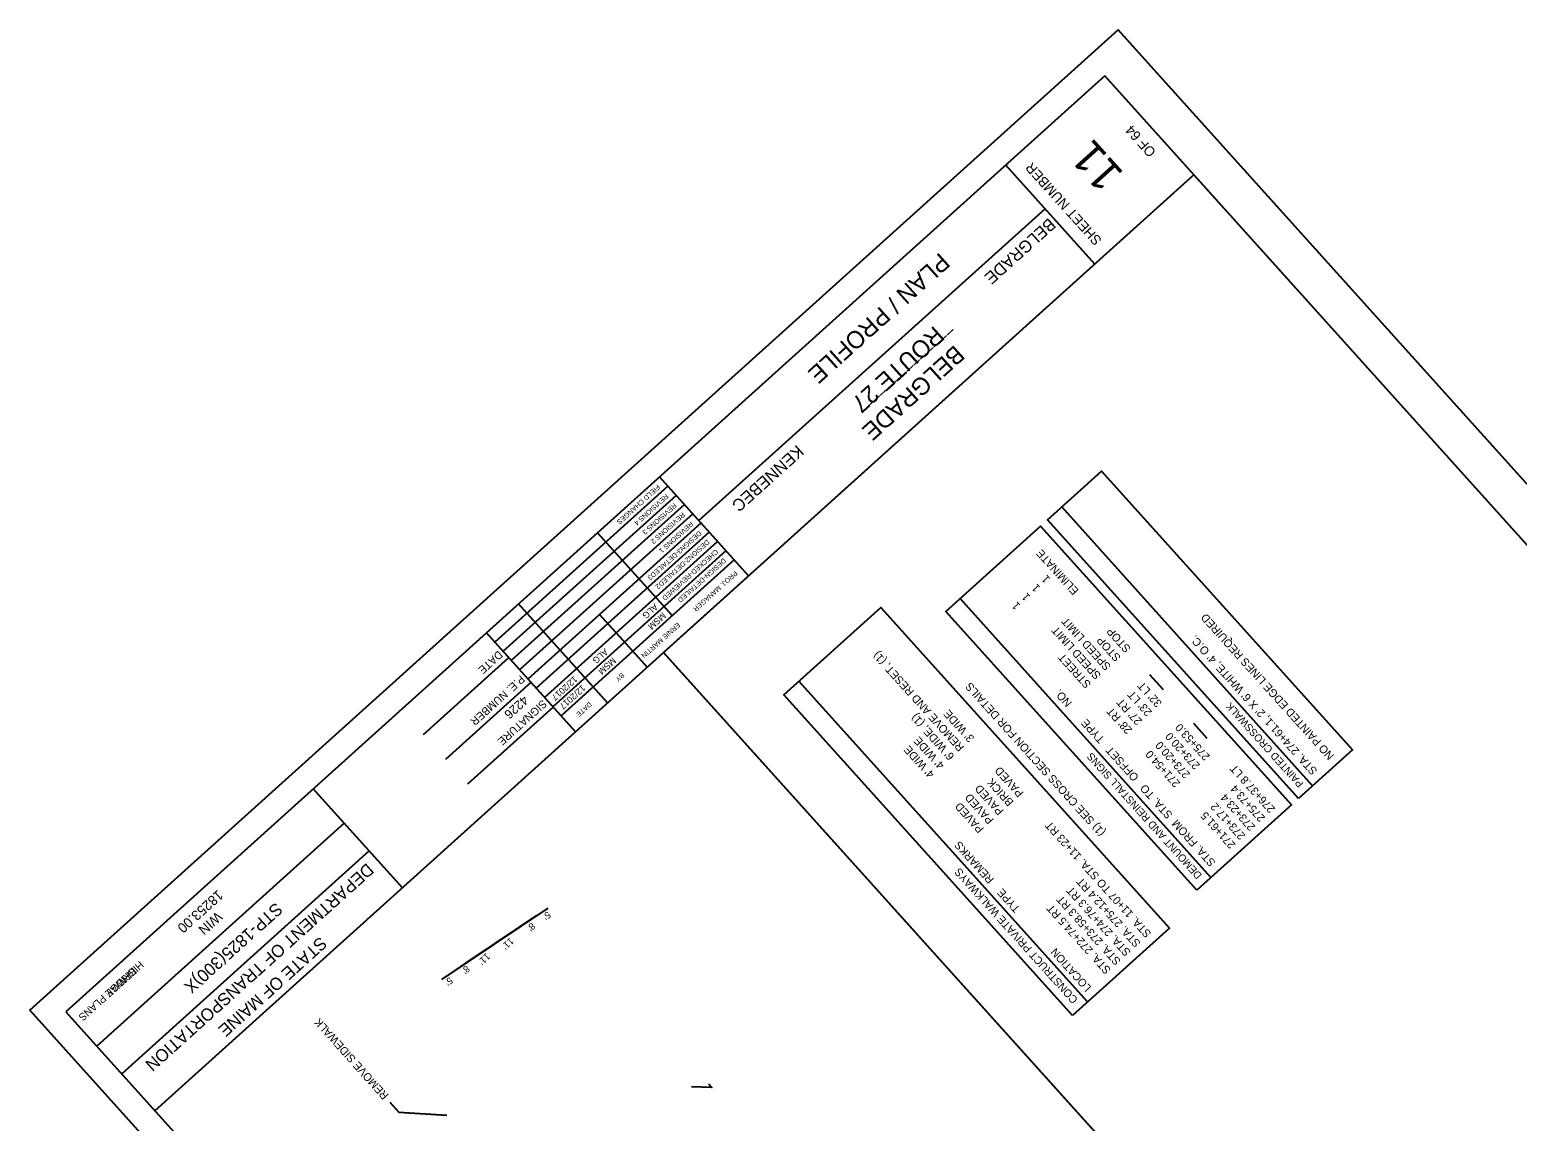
# Model space of a CAD drawing. Extents: x 1111534 to 1112511, y 616515 to 617514.
# Drawn here: x 1111534 to 1112092, y 617105 to 617514 of the extents above; entities that cross this region are included whole.
import ezdxf

# ---------------------------------------------------------------- set-up
doc = ezdxf.new("R2010")
doc.units = 0
for name, color, linetype in [('ANNOTATION', 7, 'Continuous'), ('BORDER', 7, 'Continuous'), ('BRIDGE_TITLE', 7, 'Continuous'), ('CLIPS', 7, 'Continuous'), ('HIGHWAY_TITLE', 7, 'Continuous'), ('PLOT BOUNDARY', 7, 'Continuous')]:
    doc.layers.add(name, color=color, linetype=linetype)

msp = doc.modelspace()

# ---------------------------------------------------------------- linework, layer by layer
at = {"layer": 'ANNOTATION'}
for p, q in [((1112015.33, 617230.49), (1111921.1, 617335.15)), ((1111977.12, 617196.09), (1111882.89, 617300.74)), ((1111930.75, 617149.36), (1111822.4, 617269.7)), ((1111959.27, 617266.5), (1111954.21, 617272.12)), ((1111975.72, 617248.23), (1111970.66, 617253.85)), ((1111723.81, 617181.68), (1111717.24, 617177.27)), ((1111723.81, 617181.68), (1111717.24, 617177.27)), ((1111718.41, 617178.05), (1111723.73, 617181.63)), ((1111714.68, 617175.55), (1111708.11, 617171.13)), ((1111711.91, 617173.69), (1111717.24, 617177.27)), ((1111705.55, 617169.41), (1111698.97, 617165)), ((1111702.78, 617167.55), (1111708.11, 617171.13)), ((1111698.91, 617164.95), (1111692.33, 617160.53)), ((1111693.65, 617161.42), (1111698.97, 617165))]:
    msp.add_line(p, q, dxfattribs=at)
for points in [[(1112009.98, 617225.68), (1111915.75, 617330.33), (1111936.04, 617348.6), (1112030.27, 617243.94)], [(1111971.77, 617191.27), (1111877.54, 617295.92), (1111913.11, 617327.95), (1112007.34, 617223.29)], [(1111925.12, 617144.29), (1111816.77, 617264.63), (1111853.16, 617297.39), (1111961.51, 617177.05)]]:
    msp.add_lwpolyline(points, close=True, dxfattribs=at)
for points in [[(1111728.03, 617184.52), (1111688.18, 617157.74)], [(1111788.47, 617118.57), (1111789.66, 617117.24), (1111782.02, 617117.48)], [(1111668.77, 617111.67), (1111672.15, 617107.92), (1111690.16, 617106.84)]]:
    msp.add_lwpolyline(points, dxfattribs=at)
at = {"layer": 'BORDER'}
for p, q in [((1111937.23, 617496.95), (1111547.08, 617145.66)), ((1112472.55, 616902.44), (1111937.25, 617496.96)), ((1111933.53, 617426.34), (1111900.08, 617463.49)), ((1111970.69, 617459.79), (1111580.54, 617108.5)), ((1111914.83, 617447.11), (1111784.78, 617330.01)), ((1111803.48, 617309.24), (1111770.03, 617346.39)), ((1111738.46, 617250.69), (1111705, 617287.85)), ((1112273.39, 616723.12), (1111771.54, 617280.48)), ((1111713.37, 617278.56), (1111681.23, 617249.63)), ((1111721.73, 617269.27), (1111689.6, 617240.34)), ((1111730.09, 617259.98), (1111697.96, 617231.05)), ((1111673.46, 617192.17), (1111640.01, 617229.33)), ((1111651.63, 617216.4), (1111558.74, 617132.76)), ((1111660.98, 617206.01), (1111568.09, 617122.37)), ((1111547.09, 617145.67), (1112082.4, 616551.15))]:
    msp.add_line(p, q, dxfattribs=at)
for points in [[(1111773.13, 617342.93), (1111708.12, 617284.39)], [(1111776.25, 617339.46), (1111711.23, 617280.93)], [(1111779.36, 617336), (1111714.35, 617277.46)], [(1111782.48, 617332.54), (1111717.47, 617274)], [(1111785.6, 617329.08), (1111720.58, 617270.54)], [(1111788.72, 617325.62), (1111723.7, 617267.08)], [(1111774.86, 617294.33), (1111746.8, 617325.48)], [(1111726.82, 617263.62), (1111791.83, 617322.16)], [(1111794.95, 617318.69), (1111729.94, 617260.15)], [(1111798.07, 617315.23), (1111735.68, 617259.05)], [(1111750.53, 617261.56), (1111717.08, 617298.72)], [(1111759.99, 617280.95), (1111747.53, 617294.79)], [(1111765.4, 617274.94), (1111759.99, 617280.95)], [(1111745.13, 617267.56), (1111733.06, 617256.69)]]:
    msp.add_lwpolyline(points, dxfattribs=at)
at = {"layer": 'CLIPS'}
msp.add_lwpolyline([(1112472.55, 616902.44), (1111970.7, 617459.8), (1111771.54, 617280.48), (1112273.39, 616723.12)], close=True, dxfattribs=at)
at = {"layer": 'PLOT BOUNDARY'}
msp.add_lwpolyline([(1112510.99, 616882.61), (1111942.23, 617514.28), (1111533.5, 617146.26), (1112102.26, 616514.59)], close=True, dxfattribs=at)

# ---------------------------------------------------------------- texts
at = {"layer": 'ANNOTATION'}
for s, height, rotation, p in [('ELIMINATE', 3.006, 132, (1111927.66, 617303.81)), ('1', 3.01, 132, (1111916.96, 617308.21)), ('1', 3.01, 132, (1111909.52, 617301.5)), ('1', 3.01, 132, (1111913.24, 617304.85)), ('1', 3.01, 132, (1111905.79, 617298.15)), ('SPEED LIMIT', 3.0059, 132, (1111939.76, 617275.4)), ('NO PAINTED EDGE LINES REQUIRED', 3.0059, 132, (1112023.56, 617241.84)), ('SPEED LIMIT', 3.0059, 132, (1111936.03, 617272.05)), ('STOP', 3.006, 132, (1111943.48, 617278.75)), ('STOP', 3.006, 132, (1111947.2, 617282.11)), ("STA. 274+61.1, 2' X 6' WHITE, 4' O.C.", 3.0059, 132, (1112017.28, 617236.19)), ('REMOVE AND RESET, (1)', 3.0059, 132, (1111884.69, 617245.05)), ('STREET', 3.006, 132, (1111932.31, 617268.7)), ('(1) SEE CROSS SECTION FOR DETAILS', 3.0059, 132, (1111937.64, 617213.11)), ("32' LT", 3.006, 132, (1111958.92, 617261.61)), ('4226', 3.396, 222, (1111718.9, 617264.57)), ('STA. FROM  STA. TO   OFFSET   TYPE       NO. ', 3.0059, 132, (1111979.07, 617201.79)), ("27' RT", 3.006, 132, (1111951.47, 617254.9)), ("23' LT", 3.006, 132, (1111955.2, 617258.25)), ("6' WIDE, (1)", 3.0059, 132, (1111880.97, 617241.7)), ("3' WIDE", 3.006, 132, (1111888.46, 617248.45)), ("28' RT", 3.006, 132, (1111947.75, 617251.55)), ('PAINTED CROSSWALK', 2.8055, 132, (1112012.15, 617231.4)), ('275+53.0', 3.006, 132, (1111976.96, 617241.57)), ("4' WIDE", 3.006, 132, (1111873.52, 617234.99)), ("4' WIDE", 3.006, 132, (1111877.24, 617238.35)), ('273+20.0', 3.006, 132, (1111969.51, 617234.87)), ('273+20.0', 3.006, 132, (1111973.23, 617238.22)), ('DEMOUNT AND REINSTALL SIGNS', 2.8055, 132, (1111973.94, 617196.99)), ('271+54.0', 3.006, 132, (1111965.79, 617231.52)), ('PAVED', 3.006, 132, (1111907, 617227.86)), ('276+37.8 LT', 3.0059, 132, (1112001.41, 617221.9)), ('PAVED', 3.006, 132, (1111899.51, 617221.11)), ('BRICK', 3.006, 132, (1111903.23, 617224.46)), ('275+73.4', 3.006, 132, (1111997.69, 617218.55)), ('PAVED', 3.006, 132, (1111892.06, 617214.4)), ('PAVED', 3.006, 132, (1111895.78, 617217.76)), ('273+17.2', 3.006, 132, (1111990.24, 617211.84)), ('273+23.4', 3.006, 132, (1111993.97, 617215.2)), ('271+61.5', 3.006, 132, (1111986.52, 617208.49)), ('STA. 11+07 TO STA. 11+23 RT', 3.0059, 132, (1111954.92, 617175.09)), ('LOCATION                  TYPE    REMARKS', 2.9531, 132, (1111932.4, 617154.81)), ('CONSTRUCT PRIVATE WALKWAYS', 2.9531, 132, (1111927.4, 617150.31)), ('STA. 275+12.4 RT', 3.0059, 132, (1111950.93, 617171.49)), ('STA. 274+76.3 RT', 3.0059, 132, (1111947.2, 617168.14)), ('STA. 272+74.5 RT', 3.0059, 132, (1111939.76, 617161.43)), ('STA. 273+58.3 RT', 3.0059, 132, (1111943.48, 617164.78)), ("8'", 2.55, 222.8799, (1111721.94, 617179.24)), ("5'", 2.55, 214.2567, (1111728.06, 617183.48)), ("11'", 2.55, 222.8799, (1111713.91, 617173.64)), ("11'", 2.55, 222.8799, (1111705.03, 617167.88)), ("8'", 2.55, 222.8799, (1111697.36, 617163.19)), ("5'", 2.55, 214.2567, (1111691.28, 617158.83)), ('REMOVE SIDEWALK', 3, 131.7751, (1111668.49, 617114.32))]:
    msp.add_text(s, height=height, rotation=rotation, dxfattribs=at).set_placement(p)
at = {"layer": 'BORDER'}
for s, height, rotation, p in [('OF 64', 3.726, 132, (1111956.71, 617468.52)), ('11', 12.097, 132, (1111944.71, 617460.4)), ('SHEET NUMBER', 3.7264, 132, (1111936.38, 617435.4)), ('PLAN / PROFILE', 6.5214, 222, (1111875.34, 617430.89)), ('FIELD CHANGES', 1.8637, 222, (1111769.21, 617343.66)), ('REVISIONS 4', 1.8637, 222, (1111772.33, 617340.2)), ('REVISIONS 3', 1.8637, 222, (1111775.44, 617336.73)), ('REVISIONS 2', 1.8637, 222, (1111778.56, 617333.27)), ('REVISIONS 1', 1.8637, 222, (1111781.68, 617329.81)), ('DESIGN3-DETAILED3', 1.8637, 222, (1111784.79, 617326.35)), ('DESIGN2-DETAILED2', 1.8637, 222, (1111787.79, 617323.03)), ('CHECKED-REVIEWED', 1.8637, 222, (1111791.03, 617319.42)), ('DESIGN-DETAILED', 1.8637, 222, (1111794.02, 617316.1)), ('PROJ. MANAGER', 1.8637, 222, (1111798.31, 617311.34)), ('ALG', 2.423, 222, (1111768.11, 617299.03)), ('ERNIE MARTIN', 1.8637, 222, (1111776.75, 617291.92)), ('MSM', 2.423, 222, (1111771.1, 617295.71)), ('DATE', 2.953, 222, (1111709.5, 617281.41)), ('ALG', 2.423, 222, (1111749.37, 617282.16)), ('MSM', 2.423, 222, (1111752.37, 617278.84)), ('P.E. NUMBER', 2.9528, 222, (1111717.8, 617272.19)), ('12/2017', 2.423, 222, (1111737.92, 617271.85)), ('12/2017', 2.423, 222, (1111740.91, 617268.53)), ('BY', 1.857, 222, (1111755.78, 617273.04)), ('SIGNATURE', 2.953, 222, (1111726.1, 617262.98)), ('DATE', 1.857, 222, (1111743.62, 617262.1)), ('DEPARTMENT OF TRANSPORTATION', 4.6588, 222, (1111660.09, 617201.7)), ('18253.00', 3.726, 222, (1111604.08, 617191.57)), ('STP-1825(300)X', 4.6588, 222, (1111625.86, 617186.93)), ('WIN', 3.726, 222, (1111603.71, 617183.44)), ('STATE OF MAINE', 4.6588, 222, (1111642.52, 617174.1))]:
    msp.add_text(s, height=height, rotation=rotation, dxfattribs=at).set_placement(p)
at = {"layer": 'BRIDGE_TITLE'}
for s, height, p in [('BELGRADE', 4.536, (1111916.25, 617443.88)), ('_____________', 4.5358, (1111881.11, 617400.95)), ('KENNEBEC', 4.536, (1111821.63, 617358.68)), ('BRIDGE PLANS', 2.795, (1111572.12, 617162.53))]:
    msp.add_text(s, height=height, rotation=222, dxfattribs=at).set_placement(p)
at = {"layer": 'HIGHWAY_TITLE'}
for s, height, p in [('ROUTE 27', 6.521, (1111873.24, 617403.4)), ('BELGRADE', 6.521, (1111880.88, 617396.23)), ('HIGHWAY PLANS', 2.795, (1111574.75, 617164.9))]:
    msp.add_text(s, height=height, rotation=222, dxfattribs=at).set_placement(p)

doc.saveas('drawing.dxf')
